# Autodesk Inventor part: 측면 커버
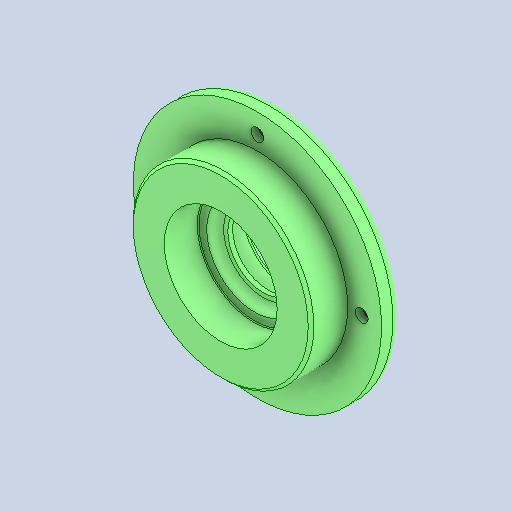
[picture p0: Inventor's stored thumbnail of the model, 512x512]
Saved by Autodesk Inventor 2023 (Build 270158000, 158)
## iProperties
Created: 2025-04
Part Number: 측면 커버
Material: 알루미늄 6061
Document SubType Name: Modeling
Designer: User
Density: 2.71 g/cm^3
Appearance: 기본값
Company: 한국ATC센터
Author: jhkim
Revision Number: 1
Sending System: Autodesk Inventor 2026
Preprocessor: ST-DEVELOPER v20.1
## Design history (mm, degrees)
feature "솔리드1"
node "솔리드2"
